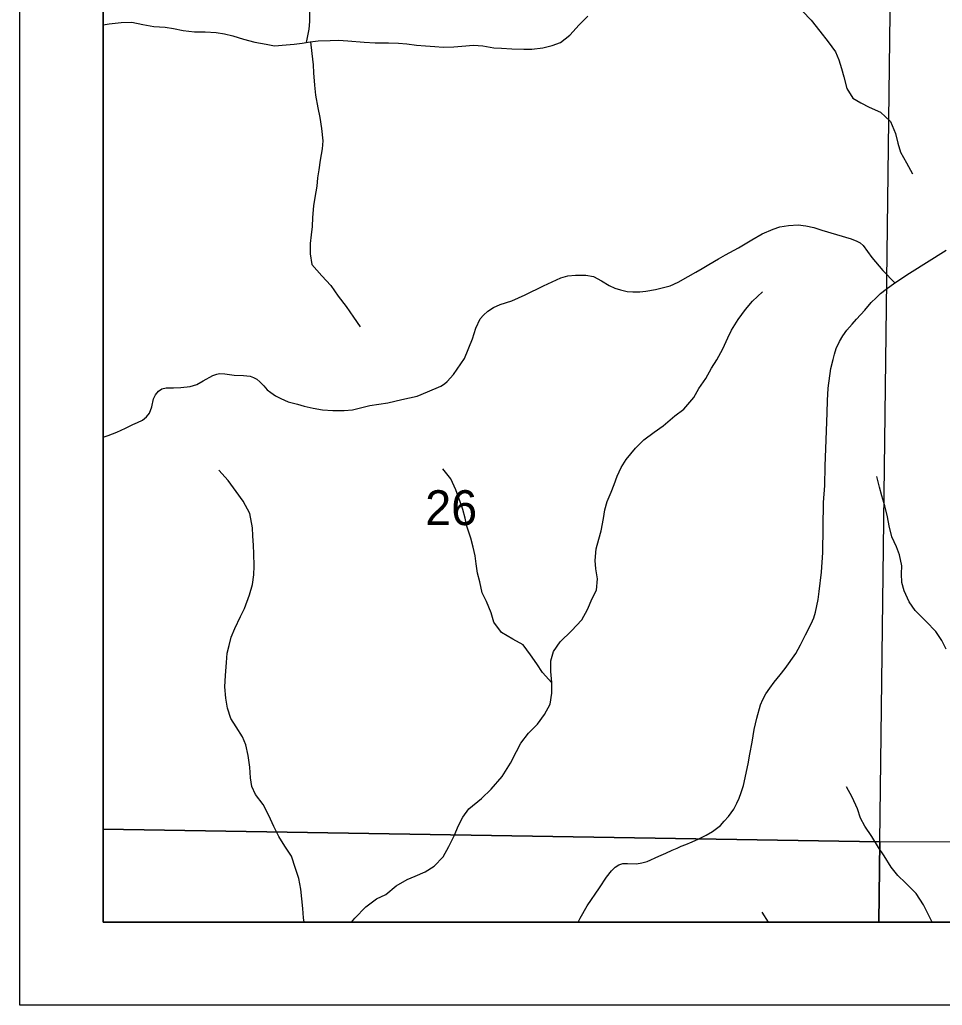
# Model space of a CAD drawing. Extents: x 0 to 34, y -8.9 to 22.
# Drawn here: x 23.617 to 24.724, y 7.004 to 8.187 of the extents above; entities that cross this region are included whole.
import ezdxf

# ---------------------------------------------------------------- set-up
doc = ezdxf.new("R2010")
doc.units = 0
for name, color, linetype in [('GM_X_Corporation', 7, 'Continuous'), ('GM_X_Minor_River', 7, 'Continuous'), ('GM_X_Section_Text', 7, 'Continuous'), ('GM_X_Township_Road', 7, 'Continuous'), ('SH_Data', 7, 'Continuous')]:
    doc.layers.add(name, color=color, linetype=linetype)

msp = doc.modelspace()

# ---------------------------------------------------------------- linework, layer by layer
at = {"layer": 'GM_X_Corporation'}
for points in [[(23.7167, 11.9654), (23.7167, 7.104), (28.7046, 7.104), (28.7123, 8.2818), (28.7238, 9.1729), (28.7308, 9.4444), (28.7377, 10.2012)], [(24.1844, 10.755), (24.1596, 9.2636), (24.0743, 9.2644), (23.7167, 9.2682), (23.7167, 7.104), (28.7046, 7.104), (28.7123, 8.2818), (28.7238, 9.1729), (28.7308, 9.4444), (28.7377, 10.2012)]]:
    msp.add_lwpolyline(points, dxfattribs=at)
for points in [[(23.7167, 8.2443), (23.7167, 7.2154), (24.6491, 7.2004), (24.6618, 8.2279)], [(24.6618, 8.2279), (25.6692, 8.2169), (25.6523, 7.1969), (24.6491, 7.2004)], [(23.7167, 7.2154), (23.7167, 7.104), (24.648, 7.104), (24.6491, 7.2004)], [(24.648, 7.104), (25.6521, 7.104), (25.6523, 7.1969), (24.6491, 7.2004)]]:
    msp.add_lwpolyline(points, close=True, dxfattribs=at)
at = {"layer": 'GM_X_Minor_River'}
msp.add_line((24.5154, 7.104), (24.5078, 7.1157), dxfattribs=at)
for points in [[(23.9607, 8.1601), (23.964, 8.176), (23.9647, 8.1855), (23.9646, 8.2094)], [(23.7167, 8.1812), (23.7241, 8.1824), (23.7385, 8.1843), (23.7511, 8.1844), (23.7644, 8.1818), (23.7776, 8.1795), (23.7913, 8.1785), (23.8012, 8.177), (23.8129, 8.1747), (23.8266, 8.1729), (23.8391, 8.1729), (23.8524, 8.1722), (23.8623, 8.1707), (23.8725, 8.1681), (23.8854, 8.1643), (23.8987, 8.1606), (23.9124, 8.158), (23.9223, 8.1561), (23.9363, 8.1573), (23.9462, 8.1581), (23.9556, 8.1593), (23.9651, 8.1608), (23.975, 8.162), (23.9894, 8.1624), (23.9993, 8.1628), (24.0103, 8.1621), (24.03, 8.1606), (24.0433, 8.1596), (24.0592, 8.1596), (24.0714, 8.1593), (24.0812, 8.1585), (24.093, 8.1571), (24.1036, 8.1563), (24.115, 8.1552), (24.1249, 8.1545), (24.1378, 8.1549), (24.1473, 8.1557), (24.1613, 8.1569), (24.1727, 8.1562), (24.1856, 8.1536), (24.1951, 8.1532), (24.2072, 8.1525), (24.2217, 8.1522), (24.2315, 8.1522), (24.2444, 8.1538), (24.2558, 8.1565), (24.2657, 8.1603), (24.277, 8.1691), (24.288, 8.1813), (24.2986, 8.1919)], [(24.5562, 8.1978), (24.5665, 8.1868), (24.5772, 8.1739), (24.5871, 8.161), (24.5958, 8.1489), (24.6, 8.1391), (24.6031, 8.1288), (24.6058, 8.119), (24.6096, 8.1049), (24.6168, 8.0932), (24.6263, 8.0875), (24.6362, 8.0823), (24.6499, 8.0766), (24.662, 8.0653), (24.6678, 8.0509), (24.6708, 8.0391), (24.6739, 8.0285), (24.6811, 8.0156), (24.6884, 8.0023)], [(23.9655, 8.1608), (23.9674, 8.1468), (23.969, 8.1331), (23.9694, 8.1236), (23.9706, 8.1088), (23.9717, 8.0967), (23.9744, 8.0815), (23.9767, 8.0701), (23.979, 8.0568), (23.9806, 8.042), (23.9795, 8.0325), (23.9772, 8.0189), (23.9757, 8.0071), (23.9742, 7.9976), (23.9731, 7.9874), (23.9709, 7.9741), (23.9694, 7.9638), (23.9682, 7.9498), (23.9675, 7.9391), (23.9664, 7.9292), (23.9653, 7.9186), (23.9653, 7.9065), (23.9672, 7.8936), (23.9794, 7.8799), (23.9901, 7.8682), (23.9988, 7.8557), (24.0083, 7.8432), (24.0171, 7.8303), (24.0251, 7.8186)], [(24.3189, 7.599), (24.3219, 7.6089), (24.3264, 7.62), (24.3302, 7.6295), (24.3336, 7.6393), (24.3385, 7.6496), (24.3446, 7.6595), (24.3559, 7.6728), (24.3658, 7.6831), (24.3783, 7.6923), (24.3889, 7.6999), (24.4029, 7.7117), (24.4139, 7.7197), (24.4256, 7.7338), (24.4316, 7.7445), (24.44, 7.7566), (24.4471, 7.7692), (24.4536, 7.7791), (24.4608, 7.7924), (24.4668, 7.8053), (24.471, 7.8148), (24.4789, 7.8274), (24.488, 7.8395), (24.4963, 7.8494), (24.5084, 7.8609)], [(23.9581, 7.104), (23.9572, 7.1089), (23.9564, 7.1203), (23.9553, 7.1317), (23.9541, 7.1434), (23.9518, 7.1563), (23.9476, 7.1681), (23.943, 7.1832), (23.935, 7.195), (23.9278, 7.2067), (23.9217, 7.2185), (23.9156, 7.2321), (23.9087, 7.245), (23.8996, 7.2571), (23.8954, 7.2666), (23.8938, 7.2772), (23.8927, 7.2901), (23.8907, 7.3038), (23.8881, 7.3167), (23.8842, 7.3265), (23.8763, 7.3383), (23.8702, 7.3485), (23.866, 7.3606), (23.864, 7.3728), (23.8629, 7.3864), (23.8636, 7.4001), (23.8647, 7.4157), (23.8658, 7.4267), (23.8681, 7.4362), (23.8703, 7.4461), (23.8749, 7.4563), (23.8817, 7.4708), (23.8866, 7.4803), (23.8926, 7.497), (23.896, 7.5092), (23.8975, 7.5209), (23.8982, 7.5312), (23.8978, 7.5464), (23.8974, 7.5562), (23.8966, 7.5676), (23.8962, 7.5775), (23.8928, 7.5946), (23.8848, 7.6093), (23.8764, 7.6211), (23.8669, 7.634), (23.8555, 7.6465)], [(24.2552, 7.3912), (24.2442, 7.4037), (24.2373, 7.4139), (24.2297, 7.4249), (24.221, 7.437), (24.2084, 7.4438), (24.1951, 7.4517), (24.1856, 7.4642), (24.1826, 7.4752), (24.1768, 7.4889), (24.1719, 7.4991), (24.1688, 7.5124), (24.1661, 7.523), (24.1646, 7.534), (24.1634, 7.5439), (24.1611, 7.5541), (24.1581, 7.5651), (24.1535, 7.5795), (24.1512, 7.589), (24.1485, 7.5992), (24.1455, 7.6087), (24.1401, 7.6231), (24.134, 7.636), (24.1245, 7.6481)], [(24.7287, 7.4316), (24.7234, 7.4422), (24.7161, 7.4528), (24.7047, 7.4649), (24.6914, 7.4781), (24.6842, 7.4883), (24.6781, 7.5016), (24.6754, 7.5115), (24.675, 7.5221), (24.6754, 7.5316), (24.6727, 7.5449), (24.6689, 7.5547), (24.6635, 7.5665), (24.6604, 7.5797), (24.6581, 7.5904), (24.6551, 7.6036), (24.6513, 7.6158), (24.6486, 7.626), (24.6455, 7.6389)], [(24.0149, 7.104), (24.0187, 7.1087), (24.0323, 7.1224), (24.0448, 7.132), (24.0562, 7.1369), (24.0687, 7.1476), (24.0819, 7.1549), (24.0914, 7.1591), (24.1035, 7.1644), (24.1142, 7.1709), (24.1248, 7.1823), (24.1316, 7.1945), (24.1387, 7.2082), (24.1429, 7.2192), (24.1486, 7.2299), (24.1557, 7.2401), (24.1709, 7.2523), (24.1826, 7.2634), (24.1959, 7.2786), (24.2057, 7.2946), (24.2129, 7.3087), (24.2182, 7.3189), (24.2273, 7.3307), (24.2382, 7.3414), (24.2466, 7.3532), (24.2534, 7.3657), (24.2552, 7.3787), (24.2552, 7.3916), (24.254, 7.4048), (24.254, 7.4178), (24.2574, 7.4288), (24.2653, 7.4406), (24.279, 7.4535), (24.2915, 7.4669), (24.2983, 7.4794), (24.3036, 7.4923), (24.3089, 7.5026), (24.3103, 7.5159), (24.308, 7.528), (24.3073, 7.5383), (24.3087, 7.5523), (24.3118, 7.5637), (24.3144, 7.5736), (24.3174, 7.5884), (24.3189, 7.599)], [(24.712, 7.104), (24.7082, 7.1111), (24.7013, 7.1247), (24.6925, 7.1384), (24.68, 7.1509), (24.6705, 7.1599), (24.6625, 7.1698), (24.6541, 7.1834), (24.6476, 7.1933), (24.6393, 7.2065), (24.6309, 7.219), (24.6259, 7.2289), (24.6221, 7.2399), (24.616, 7.2539), (24.6092, 7.2664)]]:
    msp.add_lwpolyline(points, dxfattribs=at)
at = {"layer": 'GM_X_Township_Road'}
for points in [[(23.7167, 7.6864), (23.7227, 7.6882), (23.7333, 7.6921), (23.7436, 7.6969), (23.7524, 7.7014), (23.7579, 7.7038), (23.7639, 7.7065), (23.7689, 7.7106), (23.7724, 7.7149), (23.7751, 7.7228), (23.7773, 7.7322), (23.7796, 7.7371), (23.7832, 7.7415), (23.7873, 7.7442), (23.7925, 7.7453), (23.8014, 7.7456), (23.8101, 7.746), (23.8212, 7.7472), (23.8294, 7.7495), (23.8367, 7.7539), (23.8485, 7.7601), (23.8531, 7.7619), (23.8564, 7.7626), (23.8629, 7.7622), (23.8686, 7.7614), (23.874, 7.7608), (23.8853, 7.7602), (23.8933, 7.7594), (23.8973, 7.758), (23.9011, 7.7557), (23.9049, 7.7525), (23.9095, 7.7479), (23.9138, 7.7431), (23.9179, 7.7398), (23.9237, 7.7358), (23.9301, 7.7325), (23.9387, 7.7288), (23.95, 7.7257), (23.9582, 7.7236), (23.9688, 7.7211), (23.98, 7.7189), (23.9924, 7.7182), (24.0062, 7.7182), (24.016, 7.7189), (24.037, 7.7241), (24.0587, 7.7275), (24.0753, 7.7313), (24.0937, 7.7356), (24.106, 7.7407), (24.1223, 7.7475), (24.1264, 7.7502), (24.1299, 7.753), (24.1373, 7.7615), (24.1506, 7.7806), (24.1603, 7.8042), (24.1643, 7.8172), (24.1692, 7.8281), (24.1733, 7.8326), (24.1784, 7.8373), (24.1855, 7.8419), (24.1933, 7.8454), (24.2074, 7.85), (24.2235, 7.8572), (24.2454, 7.868), (24.2662, 7.8774), (24.2745, 7.8801), (24.2838, 7.8809), (24.296, 7.8808), (24.3053, 7.879), (24.3151, 7.8741), (24.3242, 7.8683), (24.3308, 7.8652), (24.3379, 7.863), (24.3457, 7.8613), (24.3524, 7.8609), (24.361, 7.8607), (24.3683, 7.8616), (24.3798, 7.8635), (24.3972, 7.8681), (24.407, 7.8723), (24.4188, 7.8792), (24.4281, 7.8843), (24.4358, 7.8888), (24.4439, 7.8934), (24.4554, 7.9003), (24.4638, 7.9053), (24.4793, 7.9137), (24.4953, 7.9233), (24.5077, 7.9303), (24.521, 7.9361), (24.5291, 7.9389), (24.5395, 7.9404), (24.551, 7.9413), (24.5604, 7.94), (24.5698, 7.9379), (24.5795, 7.9346), (24.6147, 7.9244), (24.6216, 7.9217), (24.6253, 7.9196), (24.629, 7.9164), (24.6395, 7.9019), (24.6526, 7.8865), (24.667, 7.8716)], [(24.287, 7.104), (24.2892, 7.1086), (24.2976, 7.1233), (24.3124, 7.1449), (24.3211, 7.1578), (24.3268, 7.1655), (24.3314, 7.17), (24.3357, 7.1727), (24.3406, 7.1741), (24.3461, 7.1744), (24.3569, 7.1739), (24.3634, 7.1749), (24.3697, 7.1768), (24.3836, 7.1831), (24.3921, 7.1868), (24.3996, 7.1901), (24.4056, 7.1928), (24.4107, 7.195), (24.4161, 7.1972), (24.4236, 7.2001), (24.4318, 7.2037), (24.4406, 7.2081), (24.448, 7.2125), (24.4578, 7.2198), (24.4624, 7.2251), (24.4674, 7.2306), (24.4737, 7.2397), (24.4776, 7.2466), (24.4803, 7.2526), (24.4828, 7.2595), (24.4853, 7.268), (24.4909, 7.2941), (24.4931, 7.3057), (24.4958, 7.3201), (24.4984, 7.3351), (24.5014, 7.3489), (24.5058, 7.3647), (24.5085, 7.3711), (24.5124, 7.3781), (24.517, 7.3848), (24.5224, 7.3919), (24.5295, 7.401), (24.5353, 7.4083), (24.5484, 7.4264), (24.554, 7.4369), (24.56, 7.449), (24.5668, 7.4621), (24.5698, 7.4691), (24.572, 7.4759), (24.5751, 7.4912), (24.5764, 7.5007), (24.5792, 7.524), (24.5805, 7.5476), (24.5815, 7.6076), (24.5829, 7.6282), (24.5836, 7.6513), (24.5845, 7.6831), (24.5859, 7.7156), (24.5862, 7.7303), (24.5872, 7.7451), (24.5904, 7.7688), (24.593, 7.7793), (24.5945, 7.7857), (24.5967, 7.7928), (24.6006, 7.8009), (24.6046, 7.8077), (24.6096, 7.8145), (24.6157, 7.8218), (24.6211, 7.828), (24.631, 7.8387), (24.6386, 7.8478), (24.6446, 7.8536), (24.6497, 7.8588), (24.6567, 7.8641), (24.667, 7.8716), (24.6848, 7.883), (24.7287, 7.9106)]]:
    msp.add_lwpolyline(points, dxfattribs=at)
at = {"layer": 'SH_Data'}
for points in [[(23.6167, 14.004), (30.6167, 14.004), (30.6167, 7.004), (23.6167, 7.004)], [(23.7167, 13.904), (30.5167, 13.904), (30.5167, 7.104), (23.7167, 7.104)]]:
    msp.add_lwpolyline(points, close=True, dxfattribs=at)

# ---------------------------------------------------------------- texts
at = {"layer": 'GM_X_Section_Text'}
msp.add_text('26', height=0.04186, rotation=0, dxfattribs=at).set_placement((24.1034, 7.5806))

doc.saveas('drawing.dxf')
